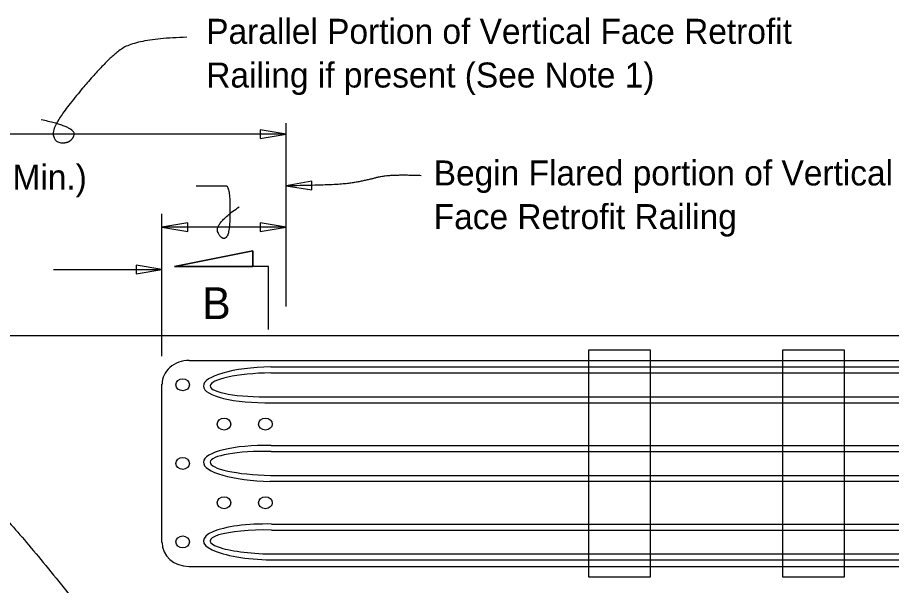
# Model space of a CAD drawing. Extents: x 0 to 41.1, y 0 to 25.9.
# Drawn here: x 9.68 to 16.72, y 9.17 to 13.75 of the extents above; entities that cross this region are included whole.
import ezdxf

# ---------------------------------------------------------------- set-up
doc = ezdxf.new("R2010")
doc.units = 0
for name, color, linetype in [('Dimension', 7, 'Continuous'), ('Miscellaneous', 7, 'Continuous'), ('TextStructures', 7, 'Continuous'), ('TrafBarrierConc', 7, 'Continuous')]:
    doc.layers.add(name, color=color, linetype=linetype)

msp = doc.modelspace()

# ---------------------------------------------------------------- linework, layer by layer
at = {"layer": 'Dimension'}
for p, q in [((11.8411, 11.4179), (11.8411, 12.8946)), ((11.8411, 12.806), (8.3411, 12.806)), ((10.8411, 11.0158), (10.8411, 12.1647)), ((11.8411, 12.056), (10.8411, 12.056)), ((10.9408, 11.7382), (11.5736, 11.8647)), ((11.5736, 11.8647), (11.5736, 11.7382)), ((9.9669, 11.7153), (10.8411, 11.7153)), ((11.7002, 11.7382), (10.9408, 11.7382)), ((11.7002, 11.2319), (11.7002, 11.7382))]:
    msp.add_line(p, q, dxfattribs=at)
for points in [[(11.8411, 12.806), (11.6328, 12.8413), (11.6328, 12.7707)], [(11.8411, 12.3898), (12.0496, 12.3564), (12.049, 12.4269)], [(10.8411, 12.056), (11.0493, 12.0207), (11.0493, 12.0913)], [(11.8411, 12.056), (11.6328, 12.0913), (11.6328, 12.0207)], [(11.5736, 11.7382), (11.5736, 11.8647), (10.9408, 11.7382)], [(10.8411, 11.7153), (10.6328, 11.7506), (10.6328, 11.68)]]:
    msp.add_lwpolyline(points, close=True, dxfattribs=at)
for points in [[(11.0409, 13.586), (10.6362, 13.5749), (10.3977, 13.4111), (9.9608, 12.888), (9.9674, 12.7357), (10.113, 12.7357), (10.1528, 12.8615), (9.8681, 12.9211)], [(12.9296, 12.4709), (12.6676, 12.482), (12.4794, 12.4303), (12.2544, 12.3934), (11.8411, 12.3897)], [(11.1158, 12.3899), (11.3242, 12.3899), (11.3891, 12.3899), (11.3891, 11.9971), (11.3245, 11.9474), (11.2599, 12.0816), (11.4637, 12.2209)], [(7.3008, 10.4958), (7.6278, 10.4958), (8.1267, 10.4958), (9.0246, 10.2686), (9.7785, 9.5258), (10.4769, 8.5946)]]:
    msp.add_open_spline(points, degree=2, dxfattribs=at)
at = {"layer": 'Miscellaneous'}
for p, q in [((11.0597, 10.9834), (20.3226, 10.9834)), ((11.7173, 10.9312), (20.3226, 10.9312)), ((11.7186, 10.8829), (20.3226, 10.8829)), ((10.8411, 9.516), (10.8411, 10.7906)), ((11.7232, 10.6901), (20.3226, 10.6901)), ((11.7244, 10.6419), (20.3226, 10.6419)), ((11.721, 10.2979), (20.3226, 10.2979)), ((11.7197, 10.2497), (20.3226, 10.2497)), ((11.7103, 10.0088), (20.3226, 10.0088)), ((11.7145, 10.0569), (20.3226, 10.0569)), ((11.7244, 9.6648), (20.3226, 9.6648)), ((11.7232, 9.6166), (20.3226, 9.6166)), ((11.717, 9.4238), (20.3226, 9.4238)), ((11.718, 9.3755), (20.3226, 9.3755)), ((11.0597, 9.3233), (20.3226, 9.3233))]:
    msp.add_line(p, q, dxfattribs=at)
for points in [[(14.2786, 9.24), (14.7786, 9.24), (14.7786, 11.0667), (14.2786, 11.0667)], [(15.8416, 9.24), (16.3416, 9.24), (16.3416, 11.0667), (15.8416, 11.0667)]]:
    msp.add_lwpolyline(points, close=True, dxfattribs=at)
for centre, major_axis, ratio, start_param, end_param in [((11.0598, 10.7906), (0.2185, 0), 0.882613, 1.570796, 3.141593), ((11.721, 10.7865), (-0.5464, -0.0102), 0.264749, 4.713933, 7.855525), ((11.721, 10.7865), (-0.4917, -0.0093), 0.196063, 4.713495, 7.855087), ((11.7174, 10.1533), (-0.5428, 0.0103), 0.266477, 4.71081, 7.852402), ((11.7174, 10.1533), (-0.4882, 0.0094), 0.197486, 4.711258, 7.85285), ((11.721, 9.5202), (-0.5464, 0.0102), 0.264749, 4.710845, 7.852438), ((11.721, 9.5202), (-0.4917, 0.0093), 0.196063, 4.711283, 7.852876), ((11.0598, 9.5161), (0.2185, 0), 0.882613, 3.141593, 4.712389)]:
    msp.add_ellipse(centre, major_axis=major_axis, ratio=ratio, start_param=start_param, end_param=end_param, dxfattribs=at)
for centre in [(11.0079, 10.7865), (11.3413, 10.4699), (11.6746, 10.4699), (11.0079, 10.1533), (11.3413, 9.8368), (11.6746, 9.8368), (11.0079, 9.5202)]:
    msp.add_ellipse(centre, major_axis=(0.0547, 0), ratio=0.882613, dxfattribs=at)
at = {"layer": 'TrafBarrierConc'}
msp.add_line((18.3647, 11.1822), (8.3411, 11.1822), dxfattribs=at)

# ---------------------------------------------------------------- texts
at = {"layer": 'Dimension'}
for s, p in [('Parallel Portion of Vertical Face Retrofit ', (11.1978, 13.5333)), ('Railing if present (See Note 1)', (11.1978, 13.1813)), ('Begin Flared portion of Vertical ', (13.0307, 12.3923)), ('Face Retrofit Railing', (13.0307, 12.0403))]:
    msp.add_text(s, height=0.2016, dxfattribs=at).set_placement(p)
at = {"layer": 'TextStructures'}
for s, height, p in [('Varies (1\'-0" Min.)', 0.2016, (8.096, 12.3585)), ('B', 0.256, (11.1662, 11.3158))]:
    msp.add_text(s, height=height, dxfattribs=at).set_placement(p)

doc.saveas('drawing.dxf')
